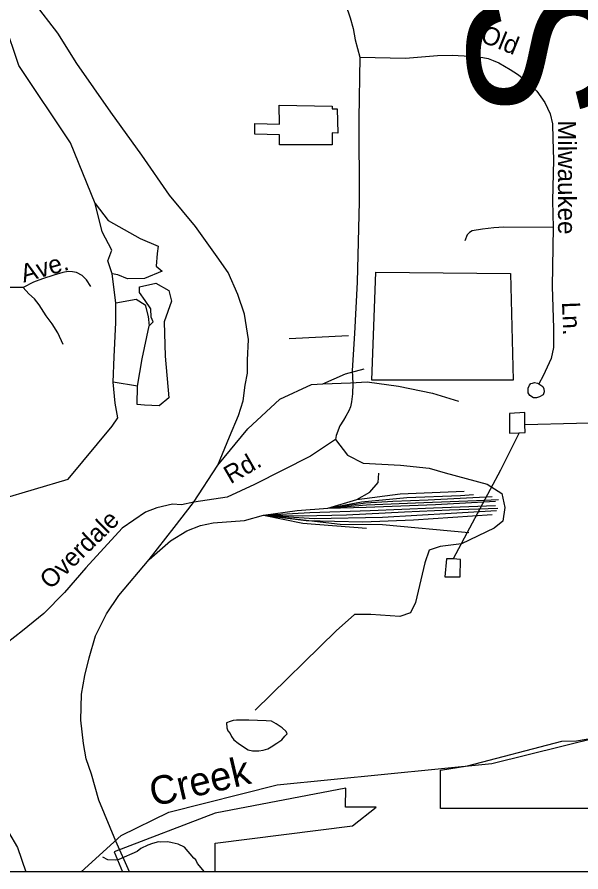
# Model space of a CAD drawing. Extents: x 1553981 to 1780076, y 812965 to 996873.
# Drawn here: x 1633867 to 1634236, y 845052 to 845613 of the extents above; entities that cross this region are included whole.
import ezdxf

# ---------------------------------------------------------------- set-up
doc = ezdxf.new("R2010")
doc.units = 0
for name, color, linetype in [('Default', 7, 'Continuous'), ('Exist Boundary Political City Limit New Hole', 7, 'Continuous'), ('Exist Cultural Warehouse Building Footprint', 7, 'Continuous'), ('Exist Hydrographic Creek Single Shore', 7, 'Continuous'), ('Exist Hydrographic Creek Single Shore Label', 7, 'Continuous'), ('Exist Hydrographic Misc Water Feature', 7, 'Continuous'), ('Exist Railroad Mainline', 7, 'Continuous'), ('Exist Railroad Siding', 7, 'Continuous'), ('Exist Road Non-System Type 51 Label', 7, 'Continuous'), ('Exist Utilities Electrical Transmission Line', 7, 'Continuous'), ('Map Preparation Border County Name Lower Right Label', 7, 'Continuous'), ('Map Preparation Border FIPS Code Label', 7, 'Continuous'), ('Map Preparation Border Revised Sign Off', 7, 'Continuous')]:
    doc.layers.add(name, color=color, linetype=linetype)

msp = doc.modelspace()

# ---------------------------------------------------------------- linework, layer by layer
at = {"layer": 'Default'}
msp.add_lwpolyline([(1632323.05, 848155.4), (1636375.85, 848155.4), (1636375.85, 845052.3), (1632323.05, 845052.3)], close=True, dxfattribs=at)
at = {"layer": 'Exist Boundary Political City Limit New Hole'}
msp.add_lwpolyline([(1634144.3, 845119.17), (1634161.98, 845121.87), (1634223.84, 845138.08), (1634233.66, 845138.33), (1634270.23, 845144.71), (1634271.22, 845093.88), (1634144.3, 845093.88)], close=True, dxfattribs=at)
at = {"layer": 'Exist Cultural Warehouse Building Footprint'}
for points in [[(1634038.52, 845555.54), (1634073.19, 845554.75), (1634073.19, 845553.17), (1634076.61, 845553.17), (1634076.87, 845537.14), (1634073.19, 845537.4), (1634073.19, 845529.51), (1634038.78, 845529.51), (1634038.78, 845536.09), (1634022.5, 845536.35), (1634022.5, 845543.45), (1634038.78, 845542.92)], [(1634101.84, 845445.82), (1634190.35, 845444.94), (1634192.12, 845374.95), (1634099.18, 845374.95)]]:
    msp.add_lwpolyline(points, close=True, dxfattribs=at)
at = {"layer": 'Exist Hydrographic Creek Single Shore'}
for points in [[(1633917.72, 845490.98), (1633901.47, 845530.71), (1633867.71, 845581.46), (1633848.59, 845637.65), (1633830.34, 845673.31)], [(1633931.38, 845425.83), (1633929, 845444.72), (1633926.1, 845453.42), (1633928.73, 845460.28), (1633922.41, 845472.41), (1633917.72, 845490.98)], [(1633930.85, 845359.89), (1633929.53, 845373.6), (1633930.32, 845390.22), (1633931.38, 845412.9), (1633931.38, 845425.83)], [(1633797.47, 845195.53), (1633804.84, 845200.72), (1633812.46, 845225.6), (1633821.33, 845273.42), (1633830.84, 845286.77), (1633855.96, 845296.93), (1633899.97, 845309.99), (1633929, 845344.85), (1633932.69, 845350.39), (1633930.85, 845359.89)], [(1633908.47, 845052.3), (1633934.71, 845076.21), (1633966.08, 845091.58), (1634037.21, 845109.42), (1634177.97, 845123.39), (1634366.09, 845170.04), (1634392.35, 845180.17), (1634445.97, 845225.45), (1634458.72, 845244.89)]]:
    msp.add_lwpolyline(points, dxfattribs=at)
at = {"layer": 'Exist Hydrographic Misc Water Feature'}
for points in [[(1633917.72, 845490.98), (1633926.36, 845479.74), (1633947.18, 845467.87), (1633959.04, 845462.86), (1633958.51, 845458.11), (1633957.72, 845449.93), (1633961.67, 845446.51), (1633950.08, 845441.76), (1633939.01, 845441.49), (1633932.69, 845444.13), (1633929, 845444.72)], [(1633946.92, 845436.32), (1633957.46, 845438.69), (1633966.16, 845433.94), (1633967.74, 845426.82), (1633962.99, 845413.37), (1633963.78, 845390.68), (1633966.16, 845363.52), (1633959.83, 845358.24), (1633950.08, 845358.5), (1633945.34, 845359.03), (1633945.6, 845371.17), (1633948.5, 845389.1), (1633953.24, 845410.73), (1633955.88, 845413.37), (1633954.56, 845416.27), (1633954.3, 845421.81), (1633950.61, 845427.35), (1633946.92, 845432.62), (1633946.92, 845436.32)], [(1633931.38, 845425.83), (1633944.55, 845428.14), (1633950.61, 845424.45), (1633952.45, 845416.8), (1633953.24, 845410.73)], [(1633945.6, 845371.17), (1633929.53, 845373.6)], [(1634003.93, 845150.14), (1634004.06, 845146.74), (1634004.85, 845144.98), (1634006.24, 845143.08), (1634007.21, 845141.2), (1634008.82, 845139.07), (1634011.55, 845136.81), (1634014.98, 845134.42), (1634018.18, 845132.44), (1634020.97, 845131.82), (1634025.25, 845131.65), (1634027.96, 845132.26), (1634031.01, 845133.16), (1634033.25, 845134.36), (1634037.03, 845136.71), (1634040.22, 845139.01), (1634042.3, 845141.38), (1634043.72, 845143.01), (1634043.09, 845144.36), (1634040.54, 845146.74), (1634036.42, 845149.43), (1634033.46, 845151.23), (1634030, 845151.5), (1634018.59, 845151.83), (1634010.57, 845151.87), (1634008.27, 845151.61), (1634006.34, 845151.1), (1634003.93, 845150.14)], [(1633989.5, 845052.3), (1633984.97, 845057.81), (1633983.74, 845060.32), (1633982.5, 845061.33), (1633976.31, 845068.63), (1633972.32, 845070.41), (1633968.33, 845071.44), (1633965.34, 845071.96), (1633960.34, 845071.76), (1633959.34, 845072.01), (1633955.34, 845071.04), (1633952.33, 845069.82), (1633947.82, 845067.61), (1633945.31, 845065.63), (1633933.29, 845060.48), (1633931.29, 845060), (1633926.05, 845060.28), (1633922.82, 845061.89)]]:
    msp.add_lwpolyline(points, dxfattribs=at)
at = {"layer": 'Exist Railroad Mainline'}
for points in [[(1634014.94, 845361.4), (1634016.09, 845371.69), (1634017.61, 845379.69), (1634017.61, 845388.08), (1634018.42, 845401.66), (1634015.68, 845418.39), (1634011.3, 845431.32), (1634004.99, 845445.66), (1633997.91, 845455.92), (1633983.69, 845475.92), (1633966.47, 845496.42), (1633948.32, 845522.65), (1633927.93, 845550.97), (1633905.62, 845582.76), (1633893.25, 845602.72), (1633877.64, 845622.91)], [(1633953.23, 845257.32), (1633969.67, 845278.27), (1633982.31, 845294.71), (1633998.23, 845319.21), (1634005.93, 845337.82), (1634011.9, 845351.88), (1634014.94, 845361.4)], [(1633940.32, 845052.3), (1633931.32, 845072.5), (1633920.18, 845099.39), (1633915.41, 845116.37), (1633911.78, 845126.5), (1633910.16, 845136.52), (1633908.39, 845151.91), (1633908.8, 845168.85), (1633910.98, 845181.26), (1633913.86, 845192.74), (1633918.06, 845207.18), (1633925.23, 845221.6), (1633933.38, 845233.74), (1633953.23, 845257.32)]]:
    msp.add_lwpolyline(points, dxfattribs=at)
at = {"layer": 'Exist Railroad Siding'}
for points in [[(1634067.18, 845372.6), (1634081.9, 845379.16), (1634094.29, 845382.45)], [(1633998.23, 845319.21), (1634017.95, 845342.99), (1634038.93, 845362.47), (1634059.66, 845372.08), (1634067.18, 845372.6)], [(1634067.18, 845372.6), (1634085.38, 845373.36), (1634096.31, 845373.85), (1634116.79, 845371.07), (1634139.03, 845366.52), (1634156.15, 845361.22)], [(1634070.52, 845290.96), (1634089.48, 845296.78), (1634098.08, 845301.59), (1634103.39, 845307.91), (1634103.89, 845313.98)], [(1634070.52, 845290.96), (1634092.52, 845295.26), (1634122.34, 845298.05), (1634157.48, 845299.31), (1634165.99, 845300.08)], [(1634089.48, 845296.78), (1634117.79, 845300.32), (1634159.76, 845302.09)], [(1634070.52, 845290.96), (1634095.21, 845294.52), (1634113.16, 845295.53), (1634136.17, 845296.54), (1634178.13, 845298.56)], [(1634070.52, 845290.96), (1634095.72, 845293.25), (1634133.38, 845294.77), (1634168.02, 845296.03), (1634182.42, 845296.79)], [(1634070.52, 845290.96), (1634095.47, 845291.73), (1634140.97, 845293.5), (1634180.4, 845295.53)], [(1634015.67, 845282.87), (1634028.31, 845286.41), (1634050.3, 845289.45), (1634070.52, 845290.96)], [(1634028.31, 845286.41), (1634058.56, 845288.19), (1634098.25, 845289.46), (1634139.7, 845291.23), (1634180.4, 845292.75)], [(1634028.31, 845286.41), (1634053.51, 845285.92), (1634082.58, 845286.67), (1634120.75, 845288.7), (1634150.32, 845289.96), (1634181.92, 845290.97)], [(1634028.31, 845286.41), (1634061.34, 845284.14), (1634106.34, 845285.16), (1634151.33, 845287.69), (1634181.16, 845289.46)], [(1633953.23, 845257.32), (1633967.14, 845269.46), (1633978.01, 845276.04), (1633986.85, 845279.58), (1633995.2, 845281.35), (1634015.67, 845282.87)], [(1634028.31, 845286.41), (1634056.29, 845282.88), (1634093.45, 845282.12), (1634126.56, 845283.39), (1634178.13, 845286.93)], [(1634028.31, 845286.41), (1634078.53, 845280.6), (1634106.34, 845280.35), (1634162.96, 845275.04)], [(1634028.31, 845286.41), (1634054.04, 845281.23), (1634095.75, 845277.94)]]:
    msp.add_lwpolyline(points, dxfattribs=at)
at = {"layer": 'Exist Utilities Electrical Transmission Line'}
for points in [[(1634199.72, 845345.59), (1634199.59, 845353.85), (1634189.57, 845353.22), (1634189.65, 845340.22), (1634195.91, 845340.39)], [(1634300.9, 845089.77), (1634302.54, 845101.25), (1634318.07, 845123.57), (1634332.29, 845142.39), (1634331.17, 845211.65), (1634329.05, 845300.69), (1634328.69, 845350.42), (1634278.7, 845347.59), (1634233.46, 845346.65), (1634199.72, 845345.59)], [(1634195.91, 845340.39), (1634199.92, 845340.58), (1634199.72, 845345.59)], [(1634195.91, 845340.39), (1634183.61, 845316.05), (1634163.4, 845277.81), (1634152.63, 845257.7)], [(1634152.63, 845257.7), (1634148.38, 845257.76), (1634147.24, 845246), (1634157.22, 845245.87), (1634157.38, 845257.38), (1634152.63, 845257.7)]]:
    msp.add_lwpolyline(points, dxfattribs=at)
at = {"layer": 'Map Preparation Border County Name Lower Right Label'}
msp.add_line((1634084.05, 845404.12), (1634045.04, 845402.18), dxfattribs=at)
for points in [[(1634022.69, 845776.65), (1634025.06, 845757.89), (1634026.95, 845746.4), (1634030.1, 845733.33), (1634031.99, 845727.03), (1634035.29, 845719.25), (1634038.75, 845710.75), (1634045.52, 845697.52), (1634056.77, 845676.11), (1634067.78, 845653.44), (1634078.17, 845631.01), (1634083.83, 845616.84), (1634085.09, 845612.75), (1634086.98, 845605.82), (1634088.24, 845598.26), (1634091.39, 845586.93)], [(1634091.39, 845586.93), (1634090.7, 845546.81), (1634091.01, 845492.33), (1634089.75, 845439.3), (1634087.86, 845405.6)], [(1634091.39, 845586.93), (1634121.29, 845586.3), (1634142.31, 845588), (1634152.06, 845588.31), (1634163.71, 845587.68), (1634167.8, 845587.05), (1634172.21, 845586.74), (1634175.67, 845586.11), (1634178.82, 845584.85), (1634182.59, 845583.27), (1634186.37, 845581.07), (1634190.15, 845578.87), (1634194.87, 845575.91), (1634201.48, 845570.87), (1634207.45, 845564.57), (1634212.8, 845557.33), (1634216.27, 845549.77), (1634217.84, 845543.16), (1634218.15, 845533.39), (1634218.47, 845519.54), (1634217.84, 845492.77), (1634218.26, 845475.21)], [(1634218.26, 845475.21), (1634185.87, 845475.49), (1634179.29, 845475), (1634171.86, 845474.1), (1634165.11, 845472.91), (1634163.34, 845471.92), (1634161.83, 845470.43), (1634160.3, 845466.45)], [(1634218.26, 845475.21), (1634217.5, 845436.48), (1634218.52, 845409.22), (1634218.41, 845396.46), (1634216.84, 845389.24), (1634211.75, 845377.79), (1634208.95, 845372.54)], [(1633914.89, 845436.55), (1633912.18, 845440.83), (1633909.21, 845443.59), (1633905.49, 845445.62), (1633902.98, 845446.14), (1633899.98, 845446.43), (1633896.49, 845445.7), (1633890.73, 845443.99), (1633883.2, 845441.57), (1633877.2, 845439.36), (1633870.41, 845435.87)], [(1633870.41, 845435.87), (1633862.84, 845435.87), (1633850.47, 845435.87), (1633834.43, 845434.96), (1633799.83, 845435.64)], [(1633896.83, 845398.42), (1633893.32, 845406.06), (1633889.54, 845412.08), (1633885.53, 845417.3), (1633880.95, 845424.41), (1633877.97, 845428.3), (1633874.3, 845431.74), (1633870.41, 845435.87)], [(1634087.86, 845405.6), (1634086.29, 845381.36), (1634086.92, 845372.85), (1634086.6, 845365.93), (1634085.97, 845360.89), (1634085.35, 845357.42), (1634084.09, 845354.9), (1634082.2, 845351.31), (1634080.62, 845348.8), (1634078.27, 845344.93), (1634075.86, 845338.78), (1634075.47, 845336.16)], [(1634208.95, 845372.54), (1634211.44, 845370.79), (1634212.18, 845369.27), (1634212.42, 845367.27), (1634211.65, 845365.28), (1634209.37, 845364.05), (1634207.38, 845363.32), (1634205.38, 845363.33), (1634202.89, 845364.86), (1634201.9, 845366.61), (1634201.92, 845367.86), (1634201.94, 845369.86), (1634202.7, 845371.62), (1634203.7, 845372.85), (1634204.7, 845373.08), (1634205.97, 845373.58), (1634207.96, 845373.06), (1634208.95, 845372.54)], [(1634075.47, 845336.16), (1634058.95, 845325.08), (1634022.2, 845306.48), (1634004.44, 845298.22), (1633982.56, 845294.91), (1633974.3, 845293.26), (1633968.52, 845293.67), (1633958.19, 845291.19), (1633950.76, 845288.3), (1633935.48, 845277.97), (1633911.53, 845251.94), (1633897.69, 845235.61), (1633884.07, 845221.97), (1633870.03, 845210.4), (1633860.12, 845202.55), (1633854.75, 845192.63), (1633853.1, 845178.58), (1633851.44, 845149.24), (1633848.97, 845098.41), (1633866.71, 845068.41), (1633872.2, 845052.3)], [(1634075.47, 845336.16), (1634083.32, 845325.83), (1634093.64, 845320.46), (1634118.01, 845319.22), (1634137, 845317.15), (1634147.32, 845314.26), (1634174.99, 845306.82), (1634184.49, 845300.62), (1634186.55, 845291.53), (1634185.32, 845282.44), (1634179.53, 845277.89), (1634158.06, 845267.56), (1634144.02, 845265.91), (1634137, 845263.43), (1634134.11, 845255.16), (1634127.92, 845229.13), (1634124.64, 845222.41), (1634117.62, 845219.93), (1634098.63, 845221.17), (1634087.89, 845221.17), (1634075.91, 845210.43), (1634022.65, 845158.36)]]:
    msp.add_lwpolyline(points, dxfattribs=at)
at = {"layer": 'Map Preparation Border FIPS Code Label'}
msp.add_lwpolyline([(1633996.55, 845052.3), (1633996.57, 845071.15), (1634086.49, 845082.58), (1634102.12, 845094.77), (1634081.91, 845094.88), (1634082.23, 845107.3), (1633996.42, 845090.82), (1633930.24, 845065.39), (1633935.62, 845052.3)], dxfattribs=at)
at = {"layer": 'Map Preparation Border Revised Sign Off'}
msp.add_lwpolyline([(1633996.55, 845052.3), (1633996.57, 845071.15), (1634086.49, 845082.58), (1634102.12, 845094.77), (1634081.91, 845094.88), (1634082.23, 845107.3), (1633996.42, 845090.82), (1633930.24, 845065.39), (1633935.62, 845052.3)], dxfattribs=at)

# ---------------------------------------------------------------- texts
at = {"layer": 'Exist Hydrographic Creek Single Shore Label'}
msp.add_text('Creek', height=18.75, rotation=13.2462, dxfattribs=at).set_placement((1633955.84, 845095.11))
at = {"layer": 'Exist Road Non-System Type 51 Label'}
for s, height, rotation, p in [('Stockton', 95, 91.9881, (1634258.89, 845547.91)), ('Old', 11.875, 338.0202, (1634169.77, 845597.45)), ('Milwaukee', 11.875, 270.0694, (1634221.38, 845545.6)), ('Ave.', 11.875, 16.002, (1633870.83, 845438.97)), ('Ln.', 11.875, 272.1478, (1634224.04, 845426.22)), ('Rd.', 11.875, 30.0997, (1634006.57, 845306.62)), ('Overdale', 11.875, 44.3852, (1633888.41, 845237.15))]:
    msp.add_text(s, height=height, rotation=rotation, dxfattribs=at).set_placement(p)

doc.saveas('drawing.dxf')
